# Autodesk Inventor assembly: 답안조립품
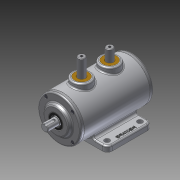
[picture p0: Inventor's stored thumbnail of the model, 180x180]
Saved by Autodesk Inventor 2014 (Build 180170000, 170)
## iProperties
Created: 2014-12
Part Number: 답안조립품
Document SubType Name: Assembly
Designer: Owner
Author: Owner
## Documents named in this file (10)
- C:\Users\Owner\Desktop\441223V1011\답안조립품.iam
- C:\Users\Owner\Desktop\441223V1011\본체.ipt
- C:\Users\Owner\Desktop\441223V1011\M4-소켓머리.ipt
- C:\Users\Owner\Desktop\441223V1011\뒷커버.ipt
- C:\Users\Owner\Desktop\441223V1011\베어링 6203.ipt
- C:\Users\Owner\Desktop\441223V1011\부시.ipt
- C:\Users\Owner\Desktop\441223V1011\슬라이더.ipt
- C:\Users\Owner\Desktop\441223V1011\앞커버.ipt
- C:\Users\Owner\Desktop\441223V1011\오일실.ipt
- C:\Users\Owner\Desktop\441223V1011\축.ipt
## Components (11 placed, 3 different names)
1. 7-베어링 6203:1
2. 8-오일실:1
3. 7-베어링 6203:2
4. 9-M4-소켓머리:1
5. 9-M4-소켓머리:3
6. 9-M4-소켓머리:4
7. 9-M4-소켓머리:5
8. 9-M4-소켓머리:2
9. 9-M4-소켓머리:6
10. 9-M4-소켓머리:7
11. 9-M4-소켓머리:8
